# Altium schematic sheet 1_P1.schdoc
size 431 x 309 mm; Symbol: Sheet-Symbol_A3; Device: Sheet-Symbol_A3; Company: 嘉立创EDA; Version: V1.0; Page Size: A3; @Project Name: My_FOC_DRV8313; @Page Count: 1; @Update Date: 2024-11-29; @Create Date: 2024-11-29; @Schematic Name: Schematic2; @Page No: 1; @Page Name: P1; @Board Name: Board2; @Create Time: 13:51:33; @Update Time: 18:25:49
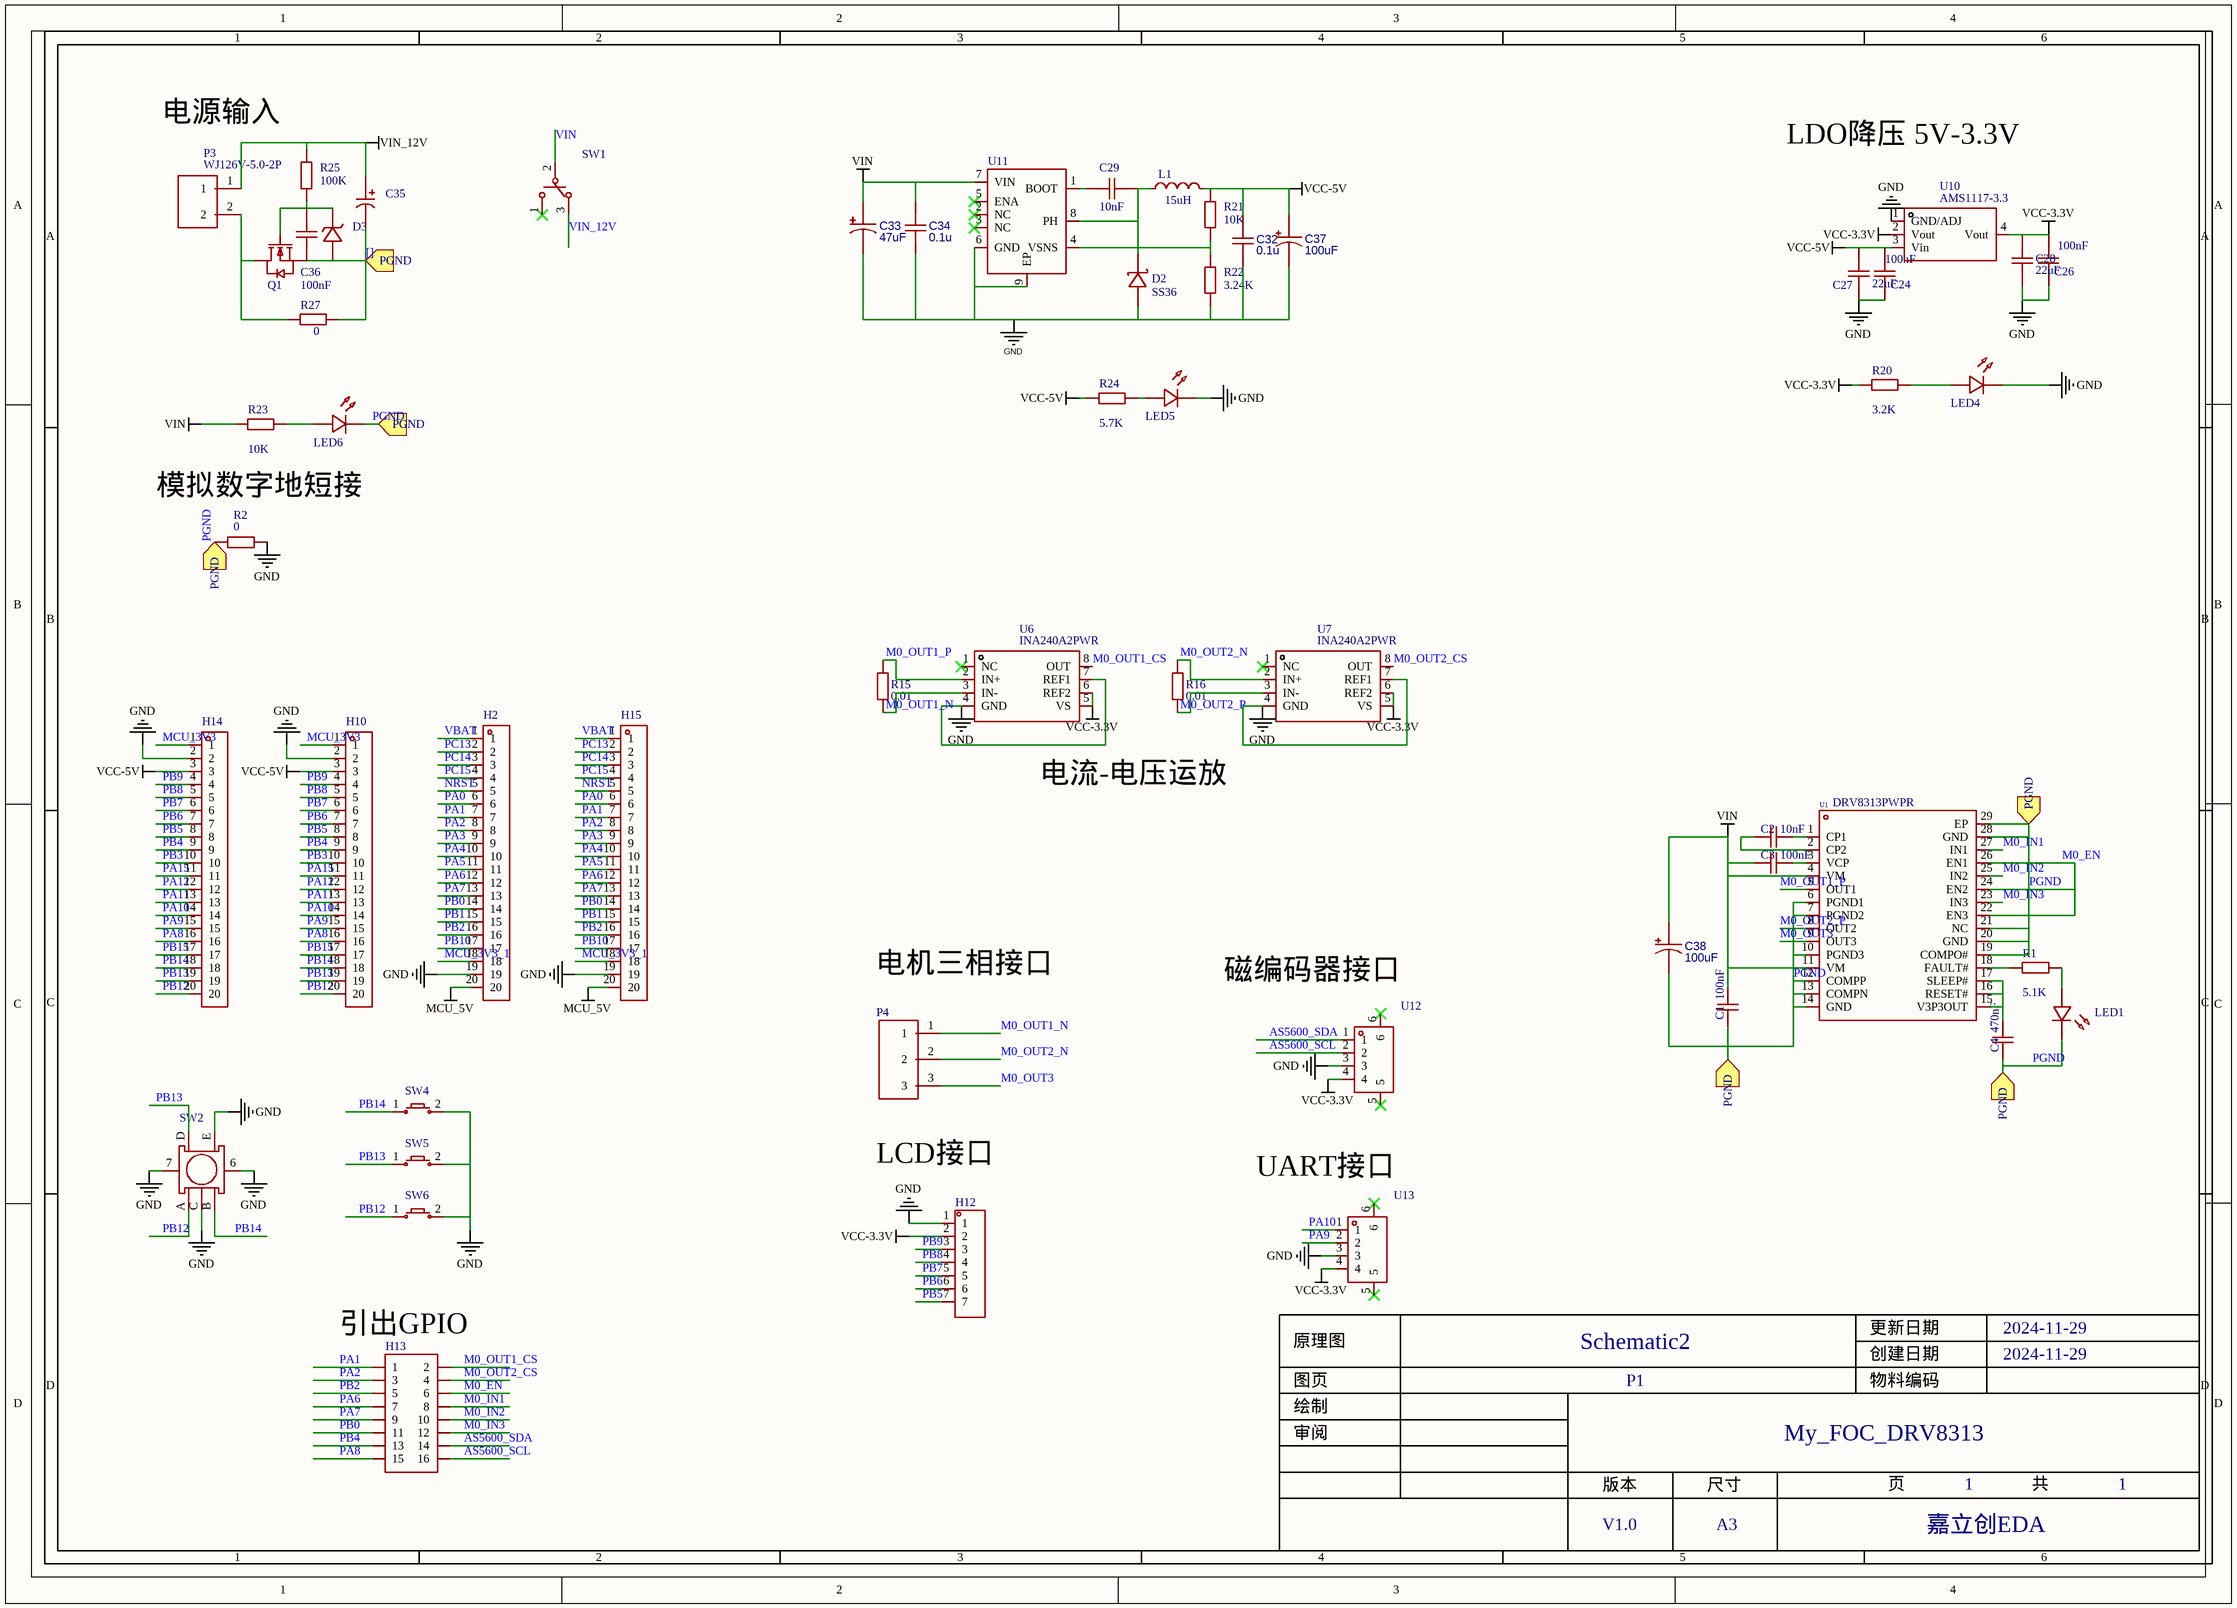
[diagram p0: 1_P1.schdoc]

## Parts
C1  100nF  [C0603]  (value not drawn)
C2  10nF  [C0603]  (value not drawn)
C3  100nF  [C0603]  (value not drawn)
C4  470nF  [C0603]  (value not drawn)
C24  100nF  [C0603]  (value not drawn)
C26  100nF  [C0603]  (value not drawn)
C27  22uF  [C0603]  (value not drawn)
C28  22uF  [C0603]  (value not drawn)
C29  10nF  [C0603]
C32  0.1u  [C0603]  (value not drawn)
C33  47uF  [CAP-SMD_BD5.0-L5.3-W5.3-FD]  (value not drawn)
C34  0.1u  [C0603]  (value not drawn)
C35  LZ1C471M0810  [CAP-SMD_BD8.0-L8.3-W8.3-LS9.3-FD-2]  (value not drawn)
C36  100nF  [C0603]
C37  100uF  [CAP-SMD_BD5.0-L5.3-W5.3-FD]  (value not drawn)
C38  100uF  [CAP-SMD_BD5.0-L5.3-W5.3-FD]  (value not drawn)
D2  SS36  [SMA_L4.3-W2.6-LS5.2-RD]  (value not drawn)
D3  ZMM12  [LL-34_L3.5-W1.5-RD]  (value not drawn)
H2  HDR-M_2.54_1x20P  [HDR-TH_20P-P2.54-V-M-1]  (value not drawn)
H10  HDR-M_2.54_1x20P  [HDR-TH_20P-P2.54-V-M-1]  (value not drawn)
H12  HDR-F_2.54_1x7P  [HDR-TH_7P-P2.54-V-F]  (value not drawn)
H13  HDR-F_2.54_2x8  [HDR-TH_16P-P2.54-V-F-R2-C8-S2.54-1]  (value not drawn)
H14  HDR-M_2.54_1x20P  [HDR-TH_20P-P2.54-V-M-1]  (value not drawn)
H15  HDR-M_2.54_1x20P  [HDR-TH_20P-P2.54-V-M-1]  (value not drawn)
L1  15uH  [IND-SMD_L4.0-W4.0]
LED1  LED_0603-R  [LED_0603]  (value not drawn)
LED4  LED_0603-R  [LED_0603]  (value not drawn)
LED5  LED_0603-R  [LED_0603]  (value not drawn)
LED6  LED_0603-R  [LED_0603]  (value not drawn)
P3  WJ126V-5.0-2P  [conn-th_wj126v-5.0-2p]  (value not drawn)
P4  WJ126V-5.0-3P  [CONN-TH_3P-P5.00_WJ126V-5.0-3P]  (value not drawn)
Q1  AO3400A  [SOT-23-3_L2.9-W1.3-P1.90-LS2.4-BR]  (value not drawn)
R1  5.1K  [R0603]
R2  0  [R0805]  (value not drawn)
R15  0.01  [R1206]  (value not drawn)
R16  0.01  [R1206]  (value not drawn)
R20  3.2K  [R0603]
R21  10K  [R0603]
R22  3.24K  [R0603]
R23  10K  [R0603]
R24  5.7K  [R0603]
R25  100K  [R0603]
R27  0  [R0805]
SW1  MT-0-103-A101-M200-RS  [SW-TH_MT-0-103-A101-M200-RS]  (value not drawn)
SW2  EC11E15244G1  [SW-TH_EC11E15244G1]  (value not drawn)
SW4  Key_SMD_3.6x6.1x2.5  [Key_SMD_3.6x6.1x2.5]  (value not drawn)
SW5  Key_SMD_3.6x6.1x2.5  [Key_SMD_3.6x6.1x2.5]  (value not drawn)
SW6  Key_SMD_3.6x6.1x2.5  [Key_SMD_3.6x6.1x2.5]  (value not drawn)
U1  DRV8313PWPR  [HTSSOP-28_L9.8-W4.5-P0.65-LS6.6-BL-EP]  (value not drawn)
U6  INA240A2PWR  [TSSOP-8_L4.4-W3.0-P0.65-LS6.4-BL]  (value not drawn)
U7  INA240A2PWR  [TSSOP-8_L4.4-W3.0-P0.65-LS6.4-BL]  (value not drawn)
U10  AMS1117-3.3  [SOT-223-3_L6.5-W3.4-P2.30-LS7.0-BR]  (value not drawn)
U11  TPS5430DDA  [ESOP-8_L4.9-W3.9-P1.27-LS6.0-BL-EP-2]  (value not drawn)
U12  XY-PH2.0-4A61  [CONN-SMD_4P-P2.00_XYECONN_XY-PH2.0-4A61]  (value not drawn)
U13  XY-PH2.0-4A61  [CONN-SMD_4P-P2.00_XYECONN_XY-PH2.0-4A61]  (value not drawn)

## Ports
PGND (in)

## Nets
GND: C24.2 C26.2 C27.1 C28.1 C32.2 C33.2 C34.2 C37.2 D2.2(A) H2.19 H10.2 H12.1 H14.2 H15.19 LED4.1(C) LED5.1(C) R2.2 R22.1 SW2.6 SW2.7 SW2.C SW2.E SW4.2 SW5.2 SW6.2 U6.4(GND) U6.7(REF1) U7.4(GND) U7.7(REF1) U10.1(GND/ADJ) U11.6(GND) U11.9(EP) U12.3 U13.3
MCU_5V: H2.20 H15.20
VCC-3.3V: C26.1 C28.2 H12.2 R20.1 U6.5(VS) U6.6(REF2) U7.5(VS) U7.6(REF2) U10.2(Vout) U10.4(Vout) U12.4 U13.4
VCC-5V: C24.1 C27.2 C32.1 C37.1 H10.3 H14.3 L1.2 R21.2 R24.1 U10.3(Vin)
VIN: C1.2 C3.1 C33.1 C34.1 C38.1 R23.1 SW1.2 U1.4(VM) U1.11(VM) U11.7(VIN)
VIN_12V: C35.1 P3.1 R25.2 SW1.3
[]: C1.1 C4.1 C35.2 C36.1 C38.2 D3.2(A) H13.6 LED1.1(C) LED6.1(C) Q1.2(S) R2.1 R27.2 U1.6(PGND1) U1.7(PGND2) U1.10(PGND3) U1.12(COMPP) U1.13(COMPN) U1.14(GND) U1.19(COMPO#) U1.20(GND) U1.21(NC) U1.22(EN3) U1.24(EN2) U1.26(EN1) U1.28(GND) U1.29(EP) ; port PGND  [also labelled M0_EN, PGND]
AS5600_SCL: H13.16 U12.2
AS5600_SDA: H13.14 U12.1
M0_IN1: H13.8 U1.27(IN1)
M0_IN2: H13.10 U1.25(IN2)
M0_IN3: H13.12 U1.23(IN3)
M0_OUT1_CS: H13.2 U6.8(OUT)
M0_OUT1_N: P4.1 R15.1 U6.3(IN-)
M0_OUT1_P: R15.2 U1.5(OUT1) U6.2(IN+)
M0_OUT2_CS: H13.4 U7.8(OUT)
M0_OUT2_N: P4.2 R16.2 U7.2(IN+)
M0_OUT2_P: R16.1 U1.8(OUT2) U7.3(IN-)
M0_OUT3: P4.3 U1.9(OUT3)
MCU_3V3: H10.1 H14.1
MCU_3V3_1: H2.18 H15.18
NRST: H2.5 H15.5
PA0: H2.6 H15.6
PA1: H2.7 H13.1 H15.7
PA2: H2.8 H13.3 H15.8
PA3: H2.9 H15.9
PA4: H2.10 H15.10
PA5: H2.11 H15.11
PA6: H2.12 H13.7 H15.12
PA7: H2.13 H13.9 H15.13
PA8: H10.16 H13.15 H14.16
PA9: H10.15 H14.15 U13.2
PA10: H10.14 H14.14 U13.1
PA11: H10.13 H14.13
PA12: H10.12 H14.12
PA15: H10.11 H14.11
PB0: H2.14 H13.11 H15.14
PB1: H2.15 H15.15
PB2: H2.16 H13.5 H15.16
PB3: H10.10 H14.10
PB4: H10.9 H13.13 H14.9
PB5: H10.8 H12.7 H14.8
PB6: H10.7 H12.6 H14.7
PB7: H10.6 H12.5 H14.6
PB8: H10.5 H12.4 H14.5
PB9: H10.4 H12.3 H14.4
PB10: H2.17 H15.17
PB12: H10.20 H14.20 SW2.A SW6.1
PB13: H10.19 H14.19 SW2.D SW5.1
PB14: H10.18 H14.18 SW2.B SW4.1
PB15: H10.17 H14.17
PC13: H2.2 H15.2
PC14: H2.3 H15.3
PC15: H2.4 H15.4
VBAT: H2.1 H15.1
NetC2_1: C2.1 U1.2(CP2)
NetC2_2: C2.2 U1.1(CP1)
NetC3_2: C3.2 U1.3(VCP)
NetC4_2: C4.2 U1.15(V3P3OUT) U1.16(RESET#) U1.17(SLEEP#)
NetC29_1: C29.1 U11.1(BOOT)
NetC29_2: C29.2 D2.1(K) L1.1 U11.8(PH)
NetC36_2: C36.2 D3.1(K) Q1.1(G) R25.1
NetLED1_2: LED1.2(A) R1.2
NetLED4_2: LED4.2(A) R20.2
NetLED5_2: LED5.2(A) R24.2
NetLED6_2: LED6.2(A) R23.2
NetP3_2: P3.2 Q1.3(D) R27.1
NetR1_1: R1.1 U1.18(FAULT#)
NetR21_1: R21.1 R22.2 U11.4(VSNS)

Not connected (* = marked no-connect by the designer): SW1 1*; U6 1(NC)*; U7 1(NC)*; U11 2(NC)* 3(NC)* 5(ENA)*; U12 5* 6*; U13 5* 6*

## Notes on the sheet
- 电源输入
- LDO降压 5V-3.3V
- 模拟数字地短接
- 电流-电压运放
- 电机三相接口
- 磁编码器接口
- LCD接口
- (near U13) UART接口
- (near H13) 引出GPIO

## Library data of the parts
C1 C3 = 0603B104K500NT: 容值:100nF;精度:±10%;额定电压:50V;材质(温度系数):X7R;; Manufacturer: FH(风华); Add into BOM: yes; Tolerance: ±10%; Voltage Rated: 50V; Temperature Coefficient: X7R
C2 = CC0603KRX7R9BB103: 容值:10nF;精度:±10%;额定电压:50V;材质(温度系数):X7R;; Manufacturer: YAGEO(国巨); Add into BOM: yes; Tolerance: ±10%; Voltage Rated: 50V; Temperature Coefficient: X7R
C4 = CL10B474KA8NNNC: 容值:470nF;精度:±10%;额定电压:25V;材质(温度系数):X7R;; Manufacturer: SAMSUNG(三星); Add into BOM: yes; Tolerance: ±10%; Voltage Rated: 25V; Temperature Coefficient: X7R
C24 C26 = CC0603KRX7R9BB104: Manufacturer: YAGEO; Convert to PCB: yes
C27 C28 = CL10A226MQ8NRNC: Manufacturer: SAMSUNG; Paste Type: base; Convert to PCB: yes
C29 C36 = CAP_0603: Symbol: CapAcitance; Convert to PCB: yes
C32 C34 = 0.1u: Convert to PCB: yes
C33 C37 C38 = FVH016ADA470M0554: 容值:47uF;精度:±20%;额定电压:16V;; Manufacturer: FOSAN(富信); Symbol: 22uF; Add into BOM: yes; Tolerance: ±20%; Rated Voltage: 16V
C35 = LZ1C471M0810: 容值: 470uF 精度: ±20% 额定电压: 16V 电容直径: 8mm 电容高度: 10.5mm 工作温度: 2000H@105℃贴片型铝电解电容; Manufacturer: JARSON(伽盛); Add into BOM: yes
D2 = SS36: Manufacturer: MDD; Paste Type: expand; Convert to PCB: yes
D3 = ZMM12_C707203: 稳压值(标称值):-;功率(Pd):500mW;; Manufacturer: Slkor(萨科微); Add into BOM: yes; Reverse Leakage Current (Ir): 100nA@9.1V; Power Dissipation: 500mW
H2 H10 H14 H15 = HDR-M_2.54_1x20P: 间距:2.54mm;总PIN位数:20;排数:1;插针结构:-;行距:-;安装类型:直插;圆针/方针:-;额定电流:-;额定电压:-;配合针长度:-;塑高:-;触头材质:黄铜;触头镀层:-;颜色:黑色;; Symbol: HDR_2.54-1x20P; Convert to PCB: yes
H12 = HDR-F_2.54_1x7P: Manufacturer: Ckmtw(灿科盟); Manufacturer Part: B-2200S07P-A120; Symbol: 220S-1*7P H=8.5MM Ytype Gold-plated; Convert to PCB: yes
H13 = HDR-F_2.54_2x8: Symbol: HDR-F-2.54_2x8; Convert to PCB: yes
L1 = SWPA4018S100MT: 电感值:10uH;精度:±20%;额定电流:840mA;饱和电流(Isat):1.6A;类型:-;; Manufacturer: Sunlord(顺络); Add into BOM: yes; Tolerance: ±20%; Rated Current: 840mA; Saturation Current (Isat): 1.6A; DC Resistance (DCR): 234mΩ
LED1 LED4-LED6 = LED_0603-R: Symbol: LED_R; Convert to PCB: yes
P3 = WJ126V-5.0-2P: Manufacturer: ReliaPro; Convert to PCB: yes
P4 = WJ126V-5.0-3P: 结构:1x3P;间距:5mm;颜色:绿色;安装方式:直插;额定电流:18A;额定电压:250V;排数:1;线规 - AWG:14~26;线规 - 平方毫米:2.5;每排PIN数:3;工作温度范围:-40℃~+105℃;; Manufacturer: KANGNEX(康奈克斯电气); Add into BOM: yes; Structure: 1x3P; Pitch: 5mm; Current Rating (Max): 18A; Voltage Rating (Max): 250V; Wire Gauge - AWG: 14~26; Wire Gauge - mm2: 2.5; Number of PINs Per Row: 3
Q1 = AO3400A_C347475: 类型:1个N沟道;漏源电压(Vdss):30V;连续漏极电流(Id):5.8A;导通电阻(RDS(on)@Vgs,Id):28mΩ@10V,5.8A;功率(Pd):1.4W;阈值电压(Vgs(th)@Id):1.4V@250uA;; Manufacturer: UMW(友台半导体); Add into BOM: yes; Type: 1个N沟道; Drain Source Voltage (Vdss): 30V; Power Dissipation (Pd): 1.4W; Total Gate Charge (Qg@Vgs): 12nC@10V; Input Capacitance (Ciss@Vds): 1.05nF@24V; Reverse Transfer Capacitance (Crss@Vds): 77pF@15V
R1 R20-R25 = Res_0603: Symbol: 电阻; Convert to PCB: yes
R2 = RM10FTN0: Manufacturer: TA-I Tech; Convert to PCB: yes
R15 R16 = RTT06R010FTP: Manufacturer: RALEC; Convert to PCB: yes
R27 = Res_0805: Symbol: 电阻; Convert to PCB: yes
SW1 = MT-0-103-A101-M200-RS: 电路结构:单刀双掷;机械寿命:-;额定电流:5A;额定电压(AC):125V;安装方式:直插;; Manufacturer: YUEN FUNG(源丰); Symbol: MT-0-103-A101-M200-RS+PJ; Add into BOM: yes; Circuit: 单刀双掷; Switch Length: 13mm; Switch Width: 8mm; Switch Height: 28.6mm; Contact Current: 5A; Voltage Rating (AC): 125V; Actuator Type: 圆柱钮柄; Pin Style: 焊片
SW2 = EC11E15244G1: Manufacturer: ALPSALPINE(阿尔卑斯阿尔派); Add into BOM: yes
SW4-SW6 = Key_SMD_3.6x6.1x2.5: Symbol: 轻触按键x2; Add into BOM: yes
U1 = DRV8313PWPR: 驱动电机类型:无刷直流BLDC;电源电压:8V~60V;输出电流:-;接口:并行;; Manufacturer: TI(德州仪器); Add into BOM: yes; Supply Voltage: 8V~60V; Interface: 并行
U6 U7 = INA240A2PWR: Manufacturer: TI; Paste Type: expand; Convert to PCB: yes
U10 = AMS1117-3.3: Manufacturer: AMS; Convert to PCB: yes
U11 = TPS5430DDA: 功能类型:降压型;输出类型:可调;输入电压:5.5V~36V;输出电压:1.221V~32.04V;输出电流(最大值):3A;; Manufacturer: TI(德州仪器); Add into BOM: yes; Function: 降压型; Output Type: 可调; Output Current (Max): 3A; Switching Frequency: 500kHz; Synchronous Rectification: 否; Number of Outputs: 1; Topology: 降压式; Switch tube (built-in/external): 内置
U12 U13 = XY-PH2.0-4A61: 插针结构:1x4P;间距:2mm;安装方式:卧贴;总PIN数:4P;排数:1;每排PIN数:4;; Manufacturer: XYECONN(辛译); Add into BOM: yes; Pins Structure: 1x4P; Pitch: 2mm; Number of PINs Per Row: 4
